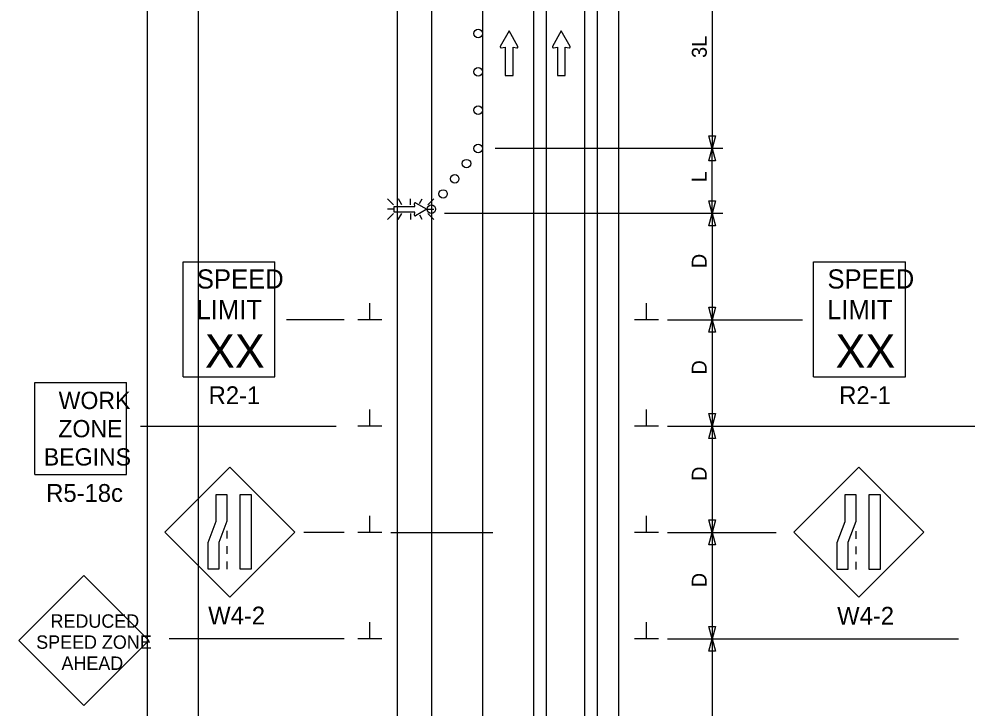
# Model space of a CAD drawing. Extents: x 16576 to 19508, y 5728 to 6974.
# Drawn here: x 16732.9 to 17178.6, y 6313.1 to 6637 of the extents above; entities that cross this region are included whole.
import ezdxf

# ---------------------------------------------------------------- set-up
doc = ezdxf.new("R2010")
doc.units = 0
for name, color, linetype in [('ALI_LEGAL_EX', 7, 'Continuous'), ('MT_SCRATCH_LEVEL_E', 7, 'Continuous'), ('PAVT_EDGE_EX', 7, 'Continuous'), ('TRAFFIC_SIGNS_PR', 7, 'Continuous'), ('TYPICAL_TEXT_DIMEN_PR', 7, 'Continuous')]:
    doc.layers.add(name, color=color, linetype=linetype)

msp = doc.modelspace()

# ---------------------------------------------------------------- linework, layer by layer
at = {"layer": 'ALI_LEGAL_EX'}
for p, q in [((16980.68, 6974.12), (16980.68, 6155.98)), ((17004.68, 6974.12), (17004.68, 6155.98)), ((16950.77, 6911.88), (16950.77, 6082.69)), ((16974.77, 6911.88), (16974.77, 6082.69)), ((16793.2, 6891.57), (16793.2, 6027.66)), ((16817.2, 6891.57), (16817.2, 6027.66))]:
    msp.add_line(p, q, dxfattribs=at)
for points in [[(16950.77, 6611.88), (16950.77, 6586.88)], [(16974.77, 6611.88), (16974.77, 6586.88)], [(16950.77, 6511.88), (16950.77, 6486.88)], [(16974.77, 6511.88), (16974.77, 6486.88)], [(16950.77, 6411.88), (16950.77, 6386.88)], [(16974.77, 6411.88), (16974.77, 6386.88)]]:
    msp.add_lwpolyline(points, dxfattribs=at)
at = {"layer": 'MT_SCRATCH_LEVEL_E'}
for p, q in [((16963.3, 6631.34), (16959.19, 6624.1)), ((16967.44, 6624.1), (16963.3, 6631.34)), ((16987.86, 6631.34), (16983.75, 6624.1)), ((16992, 6624.1), (16987.86, 6631.34)), ((16959.67, 6623.41), (16961.45, 6623.73)), ((16961.45, 6623.73), (16961.45, 6610.47)), ((16965.19, 6610.47), (16965.19, 6623.73)), ((16965.19, 6623.73), (16966.97, 6623.41)), ((16984.23, 6623.41), (16986.01, 6623.73)), ((16986.01, 6623.73), (16986.01, 6610.47)), ((16989.75, 6610.47), (16989.75, 6623.73)), ((16989.75, 6623.73), (16991.53, 6623.41)), ((16961.45, 6610.47), (16965.19, 6610.47)), ((16986.01, 6610.47), (16989.75, 6610.47))]:
    msp.add_line(p, q, dxfattribs=at)
for centre, start, end in [((16959.59, 6623.87), 150.4248, 279.9638), ((16967.04, 6623.88), 260.0362, 29.7731), ((16984.15, 6623.87), 150.4248, 279.9638), ((16991.59, 6623.88), 260.0362, 29.7731)]:
    msp.add_arc(centre, 0.463, start, end, dxfattribs=at)
at = {"layer": 'PAVT_EDGE_EX'}
for p, q in [((16910.77, 6923.28), (16910.77, 5986.88)), ((16926.77, 6923.28), (16926.77, 5986.88)), ((16998.77, 6923.28), (16998.77, 5986.88)), ((17014.77, 6923.28), (17014.77, 5986.88))]:
    msp.add_line(p, q, dxfattribs=at)
at = {"layer": 'TRAFFIC_SIGNS_PR'}
for p, q in [((16908.93, 6549.55), (16906.11, 6552.38)), ((16912.88, 6549.55), (16911.26, 6552.37)), ((16917.02, 6549.55), (16917.02, 6552.37)), ((16921.2, 6550.19), (16922.46, 6552.37)), ((16927.92, 6552.37), (16925.1, 6549.55)), ((16908.93, 6547.52), (16906.11, 6547.52)), ((16908.93, 6545.49), (16906.11, 6542.67)), ((16911.23, 6542.67), (16912.86, 6545.49)), ((16917.02, 6545.49), (16917.02, 6542.67)), ((16922.49, 6542.67), (16921.28, 6544.76)), ((16925.1, 6547.52), (16927.92, 6547.52)), ((16927.92, 6542.67), (16925.1, 6545.49)), ((16810.05, 6522.81), (16853.25, 6522.81)), ((16810.05, 6468.81), (16810.05, 6522.81)), ((16853.25, 6468.81), (16853.25, 6522.81)), ((17106.52, 6522.81), (17149.72, 6522.81)), ((17106.52, 6468.81), (17106.52, 6522.81)), ((17149.72, 6468.81), (17149.72, 6522.81)), ((16810.05, 6468.81), (16853.25, 6468.81)), ((17106.52, 6468.81), (17149.72, 6468.81)), ((16740.28, 6422.87), (16740.28, 6466.07)), ((16740.28, 6466.07), (16783.48, 6466.07)), ((16783.48, 6422.87), (16783.48, 6466.07)), ((16832.02, 6426.34), (16801.47, 6395.79)), ((16862.56, 6395.79), (16832.02, 6426.34)), ((17127.75, 6426.25), (17097.2, 6395.7)), ((17158.29, 6395.7), (17127.75, 6426.25)), ((16740.28, 6422.87), (16783.48, 6422.87)), ((16801.47, 6395.79), (16832.02, 6365.25)), ((16830.61, 6396.35), (16830.61, 6392.75)), ((16832.02, 6365.25), (16862.56, 6395.79)), ((17097.2, 6395.7), (17127.75, 6365.16)), ((17126.34, 6396.26), (17126.34, 6392.66)), ((17127.75, 6365.16), (17158.29, 6395.7)), ((16830.61, 6389.15), (16830.61, 6385.55)), ((17126.34, 6389.06), (17126.34, 6385.46)), ((16830.61, 6381.95), (16830.61, 6378.35)), ((17126.34, 6381.86), (17126.34, 6378.26)), ((16763.43, 6375.4), (16732.88, 6344.86)), ((16793.98, 6344.86), (16763.43, 6375.4)), ((16732.88, 6344.86), (16763.43, 6314.31)), ((16763.43, 6314.31), (16793.98, 6344.86))]:
    msp.add_line(p, q, dxfattribs=at)
for points in [[(16918.85, 6544.84), (16919.07, 6546.14), (16909.35, 6546.14), (16909.35, 6548.88), (16919.07, 6548.88), (16918.84, 6550.18)], [(16919.35, 6550.54), (16924.65, 6547.52), (16919.34, 6544.48)]]:
    msp.add_lwpolyline(points, dxfattribs=at)
for points in [[(16830.61, 6413.5), (16830.61, 6400.92), (16826.85, 6390.93), (16826.85, 6378.35), (16821.8, 6378.35), (16821.8, 6390.93), (16825.56, 6400.92), (16825.56, 6413.5)], [(16842.02, 6413.5), (16842.02, 6378.35), (16836.96, 6378.35), (16836.96, 6413.5)], [(17126.34, 6413.41), (17126.34, 6400.83), (17122.58, 6390.84), (17122.58, 6378.26), (17117.53, 6378.26), (17117.53, 6390.84), (17121.29, 6400.83), (17121.29, 6413.41)], [(17137.75, 6413.41), (17137.75, 6378.26), (17132.69, 6378.26), (17132.69, 6413.41)]]:
    msp.add_lwpolyline(points, close=True, dxfattribs=at)
for centre in [(16948.76, 6630.13), (16948.76, 6612.13), (16948.76, 6594.13), (16948.76, 6576.13), (16948.76, 6576.13), (16948.76, 6576.13), (16948.76, 6576.13), (16943.26, 6569), (16937.77, 6561.87), (16932.27, 6554.74), (16926.77, 6547.62)]:
    msp.add_circle(centre, 2, dxfattribs=at)
for centre, start, end in [((16919.18, 6550.24), 61.1084, 189.2692), ((16919.18, 6544.78), 170.0407, 298.5167)]:
    msp.add_arc(centre, 0.341, start, end, dxfattribs=at)
at = {"layer": 'TYPICAL_TEXT_DIMEN_PR'}
for p, q in [((17058.86, 6668.18), (17058.77, 6576.13)), ((17058.77, 6576.13), (17057.2, 6581.99)), ((17057.2, 6581.99), (17058.77, 6581.99)), ((17058.77, 6581.99), (17060.34, 6581.99)), ((17060.34, 6581.99), (17058.77, 6576.13)), ((17063.77, 6576.13), (16956.85, 6576.13)), ((17057.2, 6570.27), (17058.77, 6576.13)), ((17058.77, 6545.62), (17058.77, 6576.13)), ((17058.77, 6576.13), (17060.34, 6570.27)), ((17058.77, 6570.27), (17057.2, 6570.27)), ((17060.34, 6570.27), (17058.77, 6570.27)), ((17058.77, 6545.62), (17057.2, 6551.48)), ((17057.2, 6551.48), (17058.77, 6551.48)), ((17058.77, 6551.48), (17060.34, 6551.48)), ((17060.34, 6551.48), (17058.77, 6545.62)), ((17063.77, 6545.62), (16933.03, 6545.62)), ((17057.2, 6539.76), (17058.77, 6545.62)), ((17058.77, 6545.62), (17058.77, 6495.62)), ((17058.77, 6545.62), (17060.34, 6539.76)), ((17058.77, 6539.76), (17057.2, 6539.76)), ((17060.34, 6539.76), (17058.77, 6539.76)), ((16897.85, 6495.62), (16897.85, 6503.4)), ((17027.9, 6495.62), (17027.9, 6503.4)), ((17058.77, 6495.62), (17057.2, 6501.48)), ((17057.2, 6501.48), (17058.77, 6501.48)), ((17058.77, 6501.48), (17060.34, 6501.48)), ((17060.34, 6501.48), (17058.77, 6495.62)), ((16885.71, 6495.62), (16858.72, 6495.62)), ((16903.47, 6495.62), (16892.22, 6495.62)), ((17033.52, 6495.62), (17022.27, 6495.62)), ((17037.77, 6495.62), (17101.27, 6495.62)), ((17057.2, 6489.76), (17058.77, 6495.62)), ((17058.77, 6495.62), (17058.77, 6445.62)), ((17058.77, 6495.62), (17060.34, 6489.76)), ((17058.77, 6489.76), (17057.2, 6489.76)), ((17060.34, 6489.76), (17058.77, 6489.76)), ((16897.85, 6445.62), (16897.85, 6453.4)), ((17027.9, 6445.62), (17027.9, 6453.4)), ((17058.77, 6445.62), (17057.2, 6451.48)), ((17057.2, 6451.48), (17058.77, 6451.48)), ((17058.77, 6451.48), (17060.34, 6451.48)), ((17060.34, 6451.48), (17058.77, 6445.62)), ((16790.02, 6445.62), (16882.03, 6445.62)), ((16903.47, 6445.62), (16892.22, 6445.62)), ((17033.52, 6445.62), (17022.27, 6445.62)), ((17037.77, 6445.62), (17183, 6445.62)), ((17037.77, 6445.62), (17047.02, 6445.62)), ((17057.2, 6439.76), (17058.77, 6445.62)), ((17058.77, 6445.62), (17060.34, 6439.76)), ((17058.77, 6445.62), (17058.77, 6395.62)), ((17058.77, 6439.76), (17057.2, 6439.76)), ((17060.34, 6439.76), (17058.77, 6439.76)), ((16897.85, 6395.62), (16897.85, 6403.4)), ((17027.9, 6395.62), (17027.9, 6403.4)), ((17058.77, 6395.62), (17057.2, 6401.48)), ((17057.2, 6401.48), (17058.77, 6401.48)), ((17058.77, 6401.48), (17060.34, 6401.48)), ((17060.34, 6401.48), (17058.77, 6395.62)), ((16885.71, 6395.62), (16866.79, 6395.62)), ((16903.47, 6395.62), (16892.22, 6395.62)), ((16907.72, 6395.62), (16955.67, 6395.62)), ((17033.52, 6395.62), (17022.27, 6395.62)), ((17037.77, 6395.62), (17088.92, 6395.62)), ((17057.2, 6389.76), (17058.77, 6395.62)), ((17058.77, 6395.62), (17058.77, 6345.62)), ((17058.77, 6395.62), (17060.34, 6389.76)), ((17058.77, 6389.76), (17057.2, 6389.76)), ((17060.34, 6389.76), (17058.77, 6389.76)), ((16897.85, 6345.62), (16897.85, 6353.4)), ((17027.9, 6345.62), (17027.9, 6353.4)), ((17058.77, 6345.62), (17057.2, 6351.48)), ((17057.2, 6351.48), (17058.77, 6351.48)), ((17058.77, 6351.48), (17060.34, 6351.48)), ((17060.34, 6351.48), (17058.77, 6345.62)), ((16885.71, 6345.62), (16803.45, 6345.62)), ((16903.47, 6345.62), (16892.22, 6345.62)), ((17033.52, 6345.62), (17022.27, 6345.62)), ((17037.77, 6345.62), (17174.62, 6345.62)), ((17037.77, 6345.62), (17047.02, 6345.62)), ((17057.2, 6339.76), (17058.77, 6345.62)), ((17058.77, 6345.62), (17058.77, 6255.62)), ((17058.77, 6345.62), (17060.34, 6339.76)), ((17058.77, 6339.76), (17057.2, 6339.76)), ((17060.34, 6339.76), (17058.77, 6339.76))]:
    msp.add_line(p, q, dxfattribs=at)

# ---------------------------------------------------------------- texts
at = {"layer": 'TRAFFIC_SIGNS_PR'}
for s, height, p in [('SPEED', 9, (16816.54, 6510.28)), ('SPEED', 9, (17113.01, 6510.28)), ('LIMIT', 9, (16816.35, 6495.88)), ('LIMIT', 9, (17112.83, 6495.88)), ('XX', 15.785, (16820.3, 6473.03)), ('XX', 15.785, (17116.77, 6473.03)), ('R2-1', 8.37, (16822.06, 6455.94)), ('R2-1', 8.37, (17118.53, 6455.94)), ('WORK', 8.119, (16751.53, 6453.65)), ('ZONE', 8.119, (16751.39, 6440.37)), ('BEGINS', 8.119, (16744.56, 6427.08)), ('R5-18c', 8.37, (16745.69, 6410)), ('W4-2', 8.37, (16821.84, 6352.38)), ('REDUCED', 6.3, (16747.74, 6350.83)), ('W4-2', 8.37, (17117.57, 6352.29)), ('SPEED ZONE', 6.3, (16740.99, 6340.93)), ('AHEAD', 6.3, (16752.87, 6331.03))]:
    msp.add_text(s, height=height, dxfattribs=at).set_placement(p)
at = {"layer": 'TYPICAL_TEXT_DIMEN_PR'}
for s, p in [('3L', (17056.26, 6618.66)), ('L', (17056.21, 6560.23)), ('D', (17056.21, 6519.84)), ('D', (17056.21, 6469.84)), ('D', (17056.21, 6419.84)), ('D', (17056.21, 6369.84))]:
    msp.add_text(s, height=7, rotation=90, dxfattribs=at).set_placement(p)

doc.saveas('drawing.dxf')
